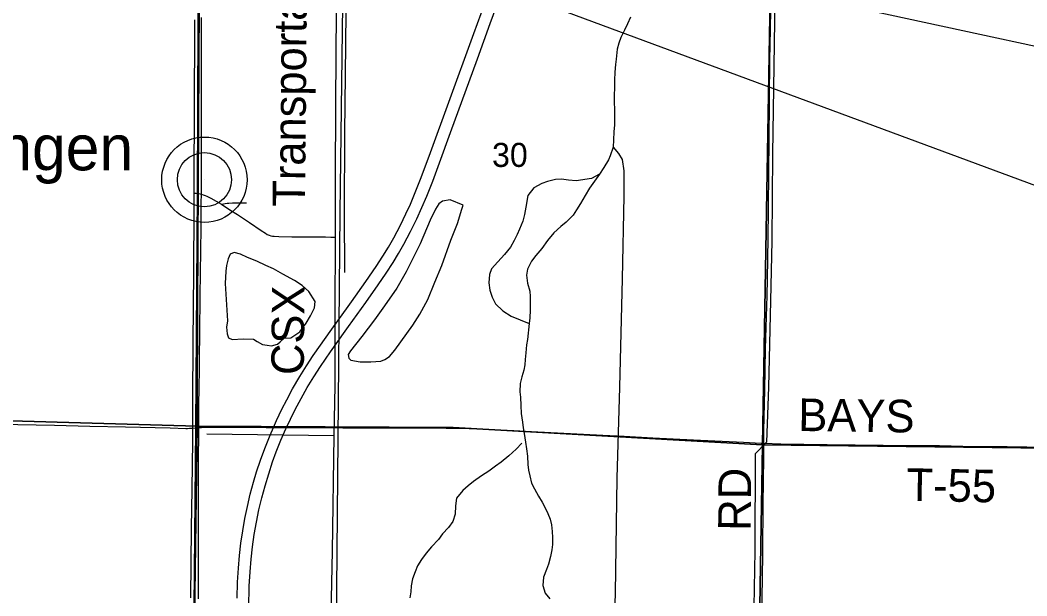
# Model space of a CAD drawing. Extents: x 0 to 39.4, y 0 to 22.
# Drawn here: x 5.077 to 6.833, y 16.092 to 17.096 of the extents above; entities that cross this region are included whole.
import ezdxf

# ---------------------------------------------------------------- set-up
doc = ezdxf.new("R2010")
doc.units = 0
for name, color, linetype in [('GM_X_Interstate_Route', 7, 'Continuous'), ('GM_X_Minor_Lake', 7, 'Continuous'), ('GM_X_Minor_River', 7, 'Continuous'), ('GM_X_Rail_Line', 7, 'Continuous'), ('GM_X_Rail_Line_Text', 7, 'Continuous'), ('GM_X_Section', 7, 'Continuous'), ('GM_X_Section_Text', 7, 'Continuous'), ('GM_X_State_Route', 7, 'Continuous'), ('GM_X_Township_Road', 7, 'Continuous'), ('GM_X_Township_Road_Text', 7, 'Continuous'), ('GM_X_Unincorporated', 7, 'Continuous'), ('GM_X_Unincorporated_Location', 7, 'Continuous'), ('GM_X_Unincorporated_Text', 7, 'Continuous'), ('SH_Data', 7, 'Continuous')]:
    doc.layers.add(name, color=color, linetype=linetype)

msp = doc.modelspace()

# ---------------------------------------------------------------- linework, layer by layer
at = {"layer": 'GM_X_Interstate_Route'}
for points in [[(5.0717, 15.3886), (5.1012, 15.3883), (5.1323, 15.3879), (5.1587, 15.3875), (5.1975, 15.3871), (5.2131, 15.3869), (5.2302, 15.3869), (5.2721, 15.386), (5.3234, 15.3852), (5.3425, 15.3852), (5.3658, 15.3852), (5.3704, 15.3852), (5.3782, 15.8208), (5.3836, 16.3856), (5.3867, 16.794), (5.3887, 17.3876)], [(5.3887, 17.3876), (5.3867, 16.794), (5.3836, 16.3856), (5.3782, 15.8208)], [(5.4758, 16.0721), (5.4768, 16.1095), (5.4781, 16.1343), (5.48, 16.156), (5.4825, 16.1777), (5.4855, 16.1992), (5.4893, 16.2207), (5.4936, 16.242), (5.4987, 16.2632), (5.5044, 16.2843), (5.5106, 16.3051), (5.5175, 16.3258), (5.5239, 16.3434), (5.5319, 16.3636), (5.5405, 16.3836), (5.5416, 16.3859), (5.5484, 16.4005), (5.5567, 16.4172), (5.567, 16.4364), (5.5778, 16.4553), (5.5892, 16.4739), (5.6011, 16.4922), (5.6187, 16.5178), (5.6438, 16.5534), (5.6498, 16.5616), (5.6803, 16.6037), (5.7018, 16.6341), (5.7157, 16.6547), (5.7275, 16.673), (5.7371, 16.689), (5.7462, 16.7052), (5.7578, 16.7272), (5.7688, 16.7494), (5.7779, 16.7692), (5.7864, 16.7891), (5.7966, 16.8151), (5.8086, 16.8471), (5.8278, 16.8997), (5.8746, 17.0282), (5.897, 17.0895), (5.9162, 17.1421)], [(5.4554, 16.0881), (5.4562, 16.116), (5.4577, 16.1408), (5.4597, 16.1624), (5.4622, 16.184), (5.4654, 16.2055), (5.4692, 16.2269), (5.4736, 16.2482), (5.4786, 16.2694), (5.4842, 16.2903), (5.4896, 16.3082), (5.4966, 16.3287), (5.5041, 16.3491), (5.5133, 16.3722), (5.5193, 16.386), (5.5244, 16.3979), (5.5336, 16.4175), (5.542, 16.4341), (5.5524, 16.4532), (5.5649, 16.4747), (5.5764, 16.4931), (5.5884, 16.5112), (5.6209, 16.5568), (5.6492, 16.5964), (5.6552, 16.6048), (5.6803, 16.6404), (5.698, 16.666), (5.7099, 16.6842), (5.7195, 16.7002), (5.7287, 16.7165), (5.7403, 16.7385), (5.7499, 16.7581), (5.7577, 16.775), (5.7661, 16.7951), (5.7763, 16.8212), (5.7925, 16.8649), (5.8248, 16.9524), (5.8682, 17.0722), (5.8875, 17.1247)]]:
    msp.add_lwpolyline(points, dxfattribs=at)
at = {"layer": 'GM_X_Minor_Lake'}
for p, q in [((5.7748, 16.7058), (5.7506, 16.6567)), ((5.4349, 16.6367), (5.4388, 16.5718))]:
    msp.add_line(p, q, dxfattribs=at)
for points in [[(5.7506, 16.6567), (5.7338, 16.6283), (5.7125, 16.5979), (5.6953, 16.5733), (5.6732, 16.5441), (5.6534, 16.5191), (5.6492, 16.5127), (5.6504, 16.5066), (5.6541, 16.5028), (5.6701, 16.5001), (5.6887, 16.5), (5.7061, 16.5015), (5.7133, 16.5045), (5.7213, 16.5094), (5.7305, 16.5204), (5.7621, 16.564), (5.7739, 16.5833), (5.7884, 16.6087), (5.8002, 16.6391), (5.8125, 16.6683), (5.8282, 16.7123), (5.8396, 16.7412), (5.8477, 16.7662), (5.85, 16.7734), (5.8272, 16.7823), (5.8136, 16.7804), (5.8075, 16.7755), (5.8014, 16.7664), (5.7922, 16.747), (5.7748, 16.7058)], [(5.4388, 16.5718), (5.4373, 16.5604), (5.438, 16.549), (5.4403, 16.5421), (5.4467, 16.5391), (5.4661, 16.5402), (5.4839, 16.5397), (5.4903, 16.5355), (5.4998, 16.5306), (5.5081, 16.529), (5.5154, 16.5279), (5.526, 16.5309), (5.5309, 16.535), (5.5378, 16.5415), (5.5495, 16.5422), (5.5651, 16.5524), (5.5762, 16.5676), (5.5838, 16.5805), (5.5907, 16.5941), (5.5918, 16.6051), (5.5809, 16.6226), (5.5692, 16.6333), (5.5555, 16.6421), (5.5351, 16.6532), (5.5188, 16.6623), (5.5055, 16.6681), (5.49, 16.6753), (5.4737, 16.6818), (5.4616, 16.6876), (5.4502, 16.6906), (5.4437, 16.688), (5.4399, 16.6797), (5.4369, 16.6683), (5.4361, 16.658), (5.4349, 16.6367)]]:
    msp.add_lwpolyline(points, dxfattribs=at)
at = {"layer": 'GM_X_Minor_River'}
for points in [[(5.6416, 18.3738), (5.6397, 18.2519), (5.6368, 17.9388), (5.6359, 17.7474), (5.6326, 17.5373), (5.6301, 17.3295), (5.6288, 17.1521), (5.6277, 17.0461), (5.6263, 16.8296), (5.6266, 16.6901), (5.626, 16.6134), (5.6259, 16.4588), (5.6242, 16.3714), (5.6213, 16.1704), (5.6181, 16.0048), (5.6172, 15.8411), (5.614, 15.6538), (5.6138, 15.5695), (5.6113, 15.4942), (5.6102, 15.3905), (5.6089, 15.3442), (5.6082, 15.2177), (5.6092, 15.1099)], [(5.6597, 18.3445), (5.6584, 18.2769), (5.6576, 18.161), (5.6566, 18.0657), (5.6555, 17.965), (5.6525, 17.8579), (5.653, 17.7762), (5.6505, 17.701), (5.6494, 17.592), (5.6494, 17.4613), (5.6469, 17.3864), (5.6467, 17.3078), (5.646, 17.2026), (5.645, 17.1091), (5.6439, 17.0001), (5.6428, 16.899), (5.6424, 16.7589), (5.6428, 16.6559)], [(6.3964, 17.5457), (6.3973, 17.3656), (6.3956, 17.2984), (6.3922, 17.0541), (6.3894, 16.8623), (6.3882, 16.7111), (6.3859, 16.6063), (6.3821, 16.4558), (6.3784, 16.3601), (6.359, 16.34), (6.3585, 16.171), (6.3562, 16.0407), (6.3531, 15.8883), (6.3459, 15.7702), (6.3414, 15.6665), (6.3377, 15.5822), (6.334, 15.4937), (6.3295, 15.3797)], [(6.1416, 17.1005), (6.1362, 17.0891), (6.1309, 17.0781), (6.1248, 17.0656), (6.1213, 17.0557), (6.1183, 17.0451), (6.1163, 17.0276), (6.1152, 17.0181), (6.1144, 17.0048), (6.1139, 16.9907), (6.1135, 16.9763), (6.1131, 16.9661), (6.1131, 16.9531), (6.1134, 16.9395), (6.1134, 16.9254), (6.1137, 16.9132), (6.1125, 16.9007), (6.1121, 16.887), (6.1113, 16.8745), (6.1062, 16.8589), (6.1029, 16.8521), (6.0953, 16.8388), (6.0876, 16.8271), (6.0701, 16.8028), (6.0625, 16.7899), (6.0541, 16.7759), (6.0476, 16.7653), (6.0415, 16.7558), (6.0293, 16.7437), (6.0198, 16.7357), (6.008, 16.7251), (5.997, 16.7115), (5.9871, 16.6978), (5.9764, 16.6853), (5.9688, 16.6755), (5.9619, 16.6614), (5.96, 16.6512), (5.9622, 16.6375), (5.966, 16.6234), (5.9667, 16.6139), (5.9667, 16.5904), (5.9659, 16.5771), (5.9651, 16.5672), (5.9619, 16.5391), (5.9604, 16.5296), (5.9588, 16.5159)], [(6.1113, 16.8745), (6.1204, 16.8631), (6.1268, 16.8528), (6.1301, 16.833), (6.13, 16.789), (6.1269, 16.645), (6.1222, 16.4562), (6.1179, 16.2974), (6.115, 16.0968), (6.1067, 15.8484), (6.0988, 15.6083), (6.0925, 15.415), (6.0913, 15.3899), (6.092, 15.3842), (6.0966, 15.3789), (6.1042, 15.3788), (6.1152, 15.3773), (6.1231, 15.3739), (6.1264, 15.3454), (6.1241, 15.3123), (6.1236, 15.1012)], [(6.0876, 16.8271), (6.0734, 16.8195), (6.047, 16.8154), (6.0337, 16.8166), (6.0212, 16.8185), (6.011, 16.8178), (5.9969, 16.8144), (5.9867, 16.811), (5.973, 16.8035), (5.9627, 16.7902), (5.9588, 16.7697), (5.9565, 16.7568), (5.9538, 16.745), (5.9481, 16.7314), (5.9439, 16.7219), (5.9389, 16.7116), (5.9325, 16.6999), (5.9218, 16.687), (5.9104, 16.6745), (5.8993, 16.6624), (5.8959, 16.6525), (5.8947, 16.6377), (5.8962, 16.6248), (5.9003, 16.6126), (5.906, 16.6012), (5.9192, 16.589), (5.9332, 16.5798), (5.9651, 16.5672)], [(5.9588, 16.5159), (5.9581, 16.5045), (5.9573, 16.495), (5.9553, 16.4856), (5.9519, 16.4742), (5.9492, 16.4624), (5.9484, 16.448), (5.9499, 16.4385), (5.9502, 16.424), (5.9509, 16.41), (5.9532, 16.3951), (5.9543, 16.3849), (5.9561, 16.375)], [(5.6242, 16.3714), (5.403, 16.3743)], [(5.9561, 16.375), (5.9584, 16.3602), (5.9602, 16.3484), (5.9617, 16.3359), (5.9624, 16.321), (5.9635, 16.3115), (5.9658, 16.3017), (5.9688, 16.2887), (5.9741, 16.2788), (5.9809, 16.2659), (5.9873, 16.2556), (5.9926, 16.2457), (5.9971, 16.2358), (6.0012, 16.2259), (6.0039, 16.2161), (6.005, 16.2047), (6.0057, 16.194), (6.0056, 16.1819), (6.0045, 16.1724), (6.0018, 16.161), (5.9983, 16.1477), (5.9953, 16.1382), (5.9899, 16.1249), (5.9884, 16.1105), (5.9929, 16.0972), (6.0008, 16.0869)], [(5.9523, 16.3587), (5.942, 16.3477), (5.9295, 16.3363), (5.9158, 16.3253), (5.9063, 16.3182), (5.8945, 16.3098), (5.8819, 16.3015), (5.8679, 16.2917), (5.8584, 16.2841), (5.8489, 16.2758), (5.8382, 16.2625), (5.8363, 16.2492), (5.8358, 16.2348), (5.8316, 16.2219), (5.824, 16.2116), (5.8137, 16.2007), (5.8065, 16.1908), (5.7943, 16.1775), (5.7852, 16.1665), (5.7772, 16.1559), (5.7703, 16.1446), (5.7661, 16.1343), (5.7615, 16.1222), (5.7592, 16.1096), (5.7584, 16.0994), (5.7565, 16.0891)]]:
    msp.add_lwpolyline(points, dxfattribs=at)
at = {"layer": 'GM_X_Rail_Line'}
for points in [[(5.3695, 15.387), (5.386, 16.3854), (5.3967, 18.3974), (5.4127, 19.8659), (5.4216, 20.4077), (5.4296, 20.9)], [(5.6115, 14.1), (5.6226, 15.3413), (5.6228, 15.3801), (5.635, 16.7601), (5.6441, 17.4388), (5.6457, 18.044), (5.6539, 18.4301), (5.6611, 19.3588), (5.6728, 20.3992), (5.6755, 20.8483), (5.6758, 20.9)]]:
    msp.add_lwpolyline(points, dxfattribs=at)
at = {"layer": 'GM_X_Section'}
for points in [[(4.3832, 17.4133), (5.3882, 17.3864), (5.386, 16.3879), (4.3694, 16.4169)], [(5.3882, 17.3864), (6.3887, 17.3403), (6.3716, 16.3557), (5.8324, 16.3859), (5.386, 16.3879)], [(7.3784, 17.3348), (7.3732, 16.344), (6.3716, 16.3557), (6.3887, 17.3403)], [(4.3694, 16.4169), (5.386, 16.3879), (5.3717, 15.3889), (4.3695, 15.415)], [(5.386, 16.3879), (5.8324, 16.3859), (6.3716, 16.3557), (6.3626, 15.7927), (6.3442, 15.3693), (5.3717, 15.3889)], [(6.3716, 16.3557), (7.3732, 16.344), (7.3525, 15.3518), (6.3741, 15.3693), (6.3442, 15.3693), (6.3626, 15.7927)]]:
    msp.add_lwpolyline(points, close=True, dxfattribs=at)
at = {"layer": 'GM_X_State_Route'}
for points in [[(5.388, 16.0869), (5.3882, 16.1833), (5.3885, 16.2268), (5.3885, 16.3201), (5.3888, 16.3855), (5.389, 16.4227), (5.3893, 16.4569), (5.3898, 16.4848), (5.3898, 16.5066), (5.3904, 16.5501), (5.3913, 16.6154), (5.3927, 16.7335), (5.393, 16.777), (5.3932, 16.7924), (5.3933, 16.7956), (5.3934, 16.92), (5.3934, 17.0505), (5.3935, 17.1003)], [(5.3748, 16.0888), (5.3763, 16.2101), (5.377, 16.2784), (5.3781, 16.3623), (5.3783, 16.3847), (5.3786, 16.4432), (5.3788, 16.524), (5.379, 16.5457), (5.3794, 16.583), (5.3804, 16.754), (5.3805, 16.7943), (5.3807, 16.8565), (5.3811, 16.9032), (5.3813, 16.9591), (5.3815, 16.9902), (5.3817, 17.0337), (5.3821, 17.071), (5.3817, 17.0959)]]:
    msp.add_lwpolyline(points, dxfattribs=at)
at = {"layer": 'GM_X_Township_Road'}
for p, q in [((5.3783, 16.3847), (5.3838, 16.3851)), ((5.3838, 16.3851), (5.3888, 16.3855))]:
    msp.add_line(p, q, dxfattribs=at)
for points in [[(6.374, 16.3582), (6.374, 16.3611), (6.374, 16.3798), (6.3755, 16.4513), (6.3769, 16.5228), (6.3799, 16.616), (6.3807, 16.644), (6.3817, 16.7155), (6.3819, 16.7652), (6.3825, 16.8336), (6.3833, 16.8833), (6.384, 16.9579), (6.3844, 17.0263), (6.3857, 17.0792), (6.387, 17.1507), (6.3876, 17.1942), (6.3896, 17.2906), (6.3901, 17.331), (6.3903, 17.3425)], [(5.3805, 16.7943), (5.3839, 16.7939), (5.3869, 16.7935)], [(5.3869, 16.7935), (5.3886, 16.7932), (5.3932, 16.7924)], [(5.3932, 16.7924), (5.3966, 16.7913), (5.3997, 16.7902), (5.4025, 16.7891), (5.4097, 16.7854), (5.4285, 16.7747)], [(5.4285, 16.7747), (5.432, 16.7755), (5.435, 16.7761), (5.4381, 16.7765), (5.4412, 16.7768), (5.4473, 16.7772), (5.4533, 16.7775), (5.4625, 16.7773), (5.472, 16.777)], [(5.4285, 16.7747), (5.443, 16.7653), (5.4563, 16.7568), (5.4773, 16.7432), (5.4974, 16.7292), (5.5049, 16.7242), (5.5081, 16.7221), (5.5112, 16.7207), (5.5141, 16.7199), (5.5172, 16.7193), (5.5203, 16.719), (5.5286, 16.7186), (5.551, 16.7182), (5.582, 16.718), (5.5975, 16.7179), (5.6099, 16.7178), (5.6191, 16.7176), (5.6254, 16.7176)], [(4.8795, 16.3945), (4.9473, 16.3933), (4.9846, 16.3922), (5.0405, 16.3914), (5.1369, 16.3896), (5.199, 16.3881), (5.2612, 16.3869), (5.3388, 16.3849), (5.3663, 16.3841), (5.3692, 16.3841), (5.3728, 16.3843), (5.3783, 16.3847)], [(5.3888, 16.3855), (5.3934, 16.3859), (5.3964, 16.3861), (5.4002, 16.3863), (5.4254, 16.3863), (5.4627, 16.3862), (5.5062, 16.386), (5.5193, 16.386), (5.5416, 16.3859), (5.6055, 16.3857), (5.6273, 16.3855), (5.6397, 16.3854), (5.6708, 16.3853), (5.7112, 16.3851), (5.7516, 16.385), (5.82, 16.3846), (5.8604, 16.3839), (5.9039, 16.3822), (5.9381, 16.3806), (5.9691, 16.3789), (6.0933, 16.3724), (6.1305, 16.3704), (6.1802, 16.368), (6.2516, 16.3644), (6.3386, 16.3599), (6.3696, 16.3583), (6.374, 16.3582)], [(6.3464, 15.369), (6.3466, 15.376), (6.3477, 15.4071), (6.3513, 15.4816), (6.3537, 15.5406), (6.3583, 15.6525), (6.3616, 15.7426), (6.3662, 15.8669), (6.3672, 15.9166), (6.3694, 16.0129), (6.3706, 16.0627), (6.3715, 16.1217), (6.3723, 16.1684), (6.3731, 16.2523), (6.3742, 16.3331), (6.374, 16.3582)], [(6.374, 16.3582), (6.4038, 16.3573), (6.4846, 16.3562), (6.6307, 16.3545), (6.6805, 16.3541), (6.7209, 16.3534), (6.7986, 16.3524), (6.867, 16.3514), (6.9882, 16.3506), (7.1095, 16.3495), (7.1499, 16.349), (7.24, 16.3485), (7.296, 16.3482), (7.3333, 16.3482), (7.3706, 16.3477), (7.3829, 16.3475)]]:
    msp.add_lwpolyline(points, dxfattribs=at)
at = {"layer": 'GM_X_Unincorporated'}
for radius in [0.0744, 0.0472]:
    msp.add_circle((5.3986, 16.8175), radius, dxfattribs=at)
at = {"layer": 'GM_X_Unincorporated_Location'}
msp.add_line((5.3986, 16.8175), (5.3986, 16.8175), dxfattribs=at)
at = {"layer": 'SH_Data'}
msp.add_lwpolyline([(9.482, 15.8329), (5.273, 17.39), (9.482, 16.4829)], close=True, dxfattribs=at)

# ---------------------------------------------------------------- texts
at = {"layer": 'GM_X_Rail_Line_Text'}
for s, height, rotation, p in [('Transportation,', 0.056629, 89.5032, (5.5739, 16.7703)), ('CSX', 0.05663, 89.4698, (5.5717, 16.477))]:
    msp.add_text(s, height=height, rotation=rotation, dxfattribs=at).set_placement(p)
at = {"layer": 'GM_X_Section_Text'}
msp.add_text('30', height=0.04186, rotation=0, dxfattribs=at).set_placement((5.9001, 16.8398))
at = {"layer": 'GM_X_Township_Road_Text'}
for s, rotation, p in [('BAYS', 359.229, (6.4338, 16.3796)), ('RD', 89.5118, (6.3511, 16.2055)), ('T-55', 358.9364, (6.6223, 16.258))]:
    msp.add_text(s, height=0.05682, rotation=rotation, dxfattribs=at).set_placement(p)
at = {"layer": 'GM_X_Unincorporated_Text'}
msp.add_text('Mungen', height=0.07898, rotation=0, dxfattribs=at).set_placement((4.8926, 16.8339))

doc.saveas('drawing.dxf')
